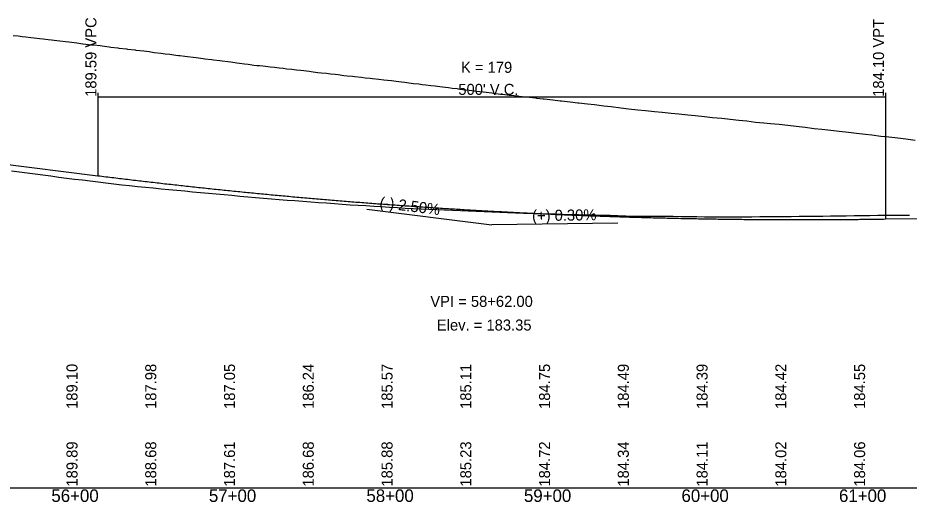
# Model space of a CAD drawing. Extents: x 1876258 to 1932803, y 754739 to 837911.
# Drawn here: x 1882224 to 1882790, y 820541 to 820848 of the extents above; entities that cross this region are included whole.
import ezdxf

# ---------------------------------------------------------------- set-up
doc = ezdxf.new("R2010")
doc.units = 0
for name, color, linetype in [('RD_DDB_GradeTX', 7, 'Continuous'), ('RD_DDB_Profile_EX', 7, 'Continuous'), ('RD_DDB_Profile_Lbl', 7, 'Continuous'), ('RD_DDB_Profile_PR', 7, 'Continuous'), ('RD_DDB_StaTX', 7, 'Continuous'), ('RD_DDB_StripGrade', 7, 'Continuous'), ('RD_DDB_VCLbl', 7, 'Continuous'), ('RD_GPK_Profile_Cell', 7, 'Continuous'), ('RD_Sketch1', 7, 'Continuous')]:
    doc.layers.add(name, color=color, linetype=linetype)

msp = doc.modelspace()

# ---------------------------------------------------------------- linework, layer by layer
at = {"layer": 'RD_DDB_GradeTX'}
for p in [(1882445.7, 820726.77), (1882605.07, 820718.06)]:
    msp.add_line(p, (1882525.08, 820716.86), dxfattribs=at)
at = {"layer": 'RD_DDB_Profile_EX'}
for points in [[(1882220.15, 820751.23), (1882225.15, 820750.53), (1882230.15, 820749.83), (1882235.15, 820749.24), (1882240.15, 820748.65), (1882245.15, 820747.96), (1882250.15, 820747.23), (1882255.15, 820746.53), (1882260.15, 820745.97), (1882265.15, 820745.4), (1882270.15, 820744.77), (1882275.15, 820744.15), (1882280.15, 820743.56), (1882285.15, 820742.97), (1882290.15, 820742.36), (1882295.15, 820741.77), (1882300.15, 820741.26), (1882305.15, 820740.74), (1882310.15, 820740.28), (1882315.15, 820739.84), (1882320.15, 820739.4), (1882325.15, 820738.94), (1882330.15, 820738.44), (1882335.15, 820737.94), (1882340.15, 820737.47), (1882345.15, 820737), (1882350.15, 820736.56), (1882355.15, 820736.12), (1882360.15, 820735.66), (1882365.15, 820735.16), (1882370.15, 820734.66), (1882375.15, 820734.18), (1882380.15, 820733.78), (1882385.15, 820733.38), (1882390.15, 820732.99)], [(1882390.15, 820732.99), (1882395.15, 820732.59), (1882400.15, 820732.25), (1882405.15, 820731.92), (1882410.15, 820731.54), (1882415.15, 820731.16), (1882420.15, 820730.78), (1882425.15, 820730.4), (1882430.15, 820730.03), (1882435.15, 820729.67), (1882440.15, 820729.35), (1882445.15, 820729.09), (1882450.15, 820728.77), (1882455.15, 820728.46), (1882460.15, 820728.16), (1882465.15, 820727.86), (1882470.15, 820727.54), (1882475.15, 820727.22), (1882480.15, 820726.97), (1882485.15, 820726.75), (1882490.15, 820726.57), (1882495.15, 820726.4), (1882500.15, 820726.21), (1882505.15, 820726.03), (1882510.15, 820725.81), (1882515.15, 820725.59), (1882520.15, 820725.37), (1882525.15, 820725.21), (1882530.15, 820724.97), (1882535.15, 820724.72), (1882540.15, 820724.56), (1882545.15, 820724.4), (1882550.15, 820724.25), (1882555.15, 820724.11), (1882560.15, 820723.97), (1882565.15, 820723.83), (1882570.15, 820723.68), (1882575.15, 820723.51), (1882580.15, 820723.39), (1882585.15, 820723.28), (1882590.15, 820723.16), (1882595.15, 820723.05), (1882600.15, 820722.94), (1882605.15, 820722.8), (1882610.15, 820722.65), (1882615.15, 820722.5), (1882620.15, 820722.43), (1882625.15, 820722.38), (1882630.15, 820722.36), (1882635.15, 820722.35), (1882640.15, 820722.32), (1882645.15, 820722.25), (1882650.15, 820722.18), (1882655.15, 820722.11), (1882660.15, 820722.08), (1882665.15, 820722.07), (1882670.15, 820722.06), (1882675.15, 820722.04), (1882680.15, 820722.05), (1882685.15, 820722.05), (1882690.15, 820722.07), (1882695.15, 820722.09), (1882700.15, 820722.11), (1882705.15, 820722.14), (1882710.15, 820722.17), (1882715.15, 820722.24), (1882720.15, 820722.31), (1882725.15, 820722.38), (1882730.15, 820722.45), (1882735.15, 820722.51), (1882740.15, 820722.57), (1882745.15, 820722.64), (1882750.15, 820722.7), (1882755.15, 820722.77), (1882760.15, 820722.84), (1882765.15, 820722.91), (1882770.15, 820722.97), (1882775.15, 820722.99), (1882780.15, 820723), (1882785.15, 820723.01), (1882790.15, 820723.03)]]:
    msp.add_lwpolyline(points, dxfattribs=at)
at = {"layer": 'RD_DDB_Profile_PR'}
for p, q in [((1881558.08, 820837.6), (1882275.08, 820748.07)), ((1882775.08, 820720.61), (1883513.81, 820731.69))]:
    msp.add_line(p, q, dxfattribs=at)
msp.add_spline([(1882275.08, 820748.07), (1882285.08, 820746.84), (1882295.08, 820745.63), (1882305.08, 820744.45), (1882315.08, 820743.3), (1882325.08, 820742.18), (1882335.08, 820741.08), (1882345.08, 820740.02), (1882355.08, 820738.98), (1882365.08, 820737.97), (1882375.08, 820736.98), (1882385.08, 820736.03), (1882395.08, 820735.1), (1882405.08, 820734.2), (1882415.08, 820733.33), (1882425.08, 820732.49), (1882435.08, 820731.67), (1882445.08, 820730.89), (1882455.08, 820730.13), (1882465.08, 820729.4), (1882475.08, 820728.69), (1882485.08, 820728.02), (1882495.08, 820727.37), (1882505.08, 820726.75), (1882515.08, 820726.16), (1882525.08, 820725.6), (1882535.08, 820725.06), (1882545.08, 820724.55), (1882555.08, 820724.08), (1882565.08, 820723.62), (1882575.08, 820723.2), (1882585.08, 820722.8), (1882595.08, 820722.44), (1882605.08, 820722.1), (1882615.08, 820721.79), (1882625.08, 820721.5), (1882635.08, 820721.25), (1882645.08, 820721.02), (1882655.08, 820720.82), (1882665.08, 820720.65), (1882675.08, 820720.5), (1882685.08, 820720.39), (1882695.08, 820720.3), (1882705.08, 820720.24), (1882715.08, 820720.21), (1882725.08, 820720.21), (1882735.08, 820720.23), (1882745.08, 820720.28), (1882755.08, 820720.36), (1882765.08, 820720.47), (1882775.08, 820720.61)], degree=3, dxfattribs=at)
at = {"layer": 'RD_DDB_VCLbl'}
for p, q in [((1882275.08, 820800.57), (1882275.08, 820748.07)), ((1882775.08, 820800.57), (1882775.08, 820720.61)), ((1882275.08, 820798.07), (1882775.08, 820798.07))]:
    msp.add_line(p, q, dxfattribs=at)
at = {"layer": 'RD_GPK_Profile_Cell'}
msp.add_line((1878363.08, 820550.13), (1884763.08, 820550.13), dxfattribs=at)
at = {"layer": 'RD_Sketch1'}
msp.add_lwpolyline([(1882221.33, 820837), (1882224.33, 820836.68), (1882226.87, 820836.38), (1882229.17, 820836.11), (1882232.39, 820835.75), (1882234.62, 820835.51), (1882237.92, 820835.13), (1882240.2, 820834.86), (1882243.46, 820834.45), (1882245.65, 820834.16), (1882248.97, 820833.77), (1882250.92, 820833.54), (1882254.48, 820833.14), (1882256.58, 820832.9), (1882260.02, 820832.48), (1882261.71, 820832.27), (1882265.55, 820831.79), (1882267.28, 820831.57), (1882271.05, 820831.14), (1882272.4, 820830.99), (1882276.56, 820830.56), (1882277.77, 820830.44), (1882282.14, 820829.81), (1882283.18, 820829.66), (1882287.64, 820829.11), (1882288.4, 820829.01), (1882293.14, 820828.5), (1882293.86, 820828.42), (1882298.68, 820827.82), (1882299.08, 820827.77), (1882304.14, 820827.22), (1882304.21, 820827.21), (1882307.5, 820826.79), (1882309.77, 820826.43), (1882310.84, 820826.26), (1882315.25, 820825.72), (1882317.63, 820825.43), (1882320.77, 820825.05), (1882324.6, 820824.6), (1882326.29, 820824.41), (1882327, 820824.32), (1882330.19, 820823.9), (1882331.83, 820823.69), (1882335.51, 820823.21), (1882337.35, 820822.97), (1882341.83, 820822.41), (1882342.87, 820822.28), (1882347.3, 820821.72), (1882348.4, 820821.58), (1882352.5, 820821.06), (1882353.91, 820820.9), (1882357.49, 820820.48), (1882359.45, 820820.22), (1882363.24, 820819.73), (1882364.99, 820819.48), (1882368.18, 820819.02), (1882370.5, 820818.71), (1882374.12, 820818.22), (1882375.98, 820818.04), (1882377.7, 820817.87), (1882379.67, 820817.68), (1882381.51, 820817.47), (1882384.48, 820817.14), (1882387.04, 820816.86), (1882390.09, 820816.52), (1882392.57, 820816.24), (1882395, 820815.95), (1882398.09, 820815.59), (1882401.08, 820815.24), (1882403.61, 820814.95), (1882405.74, 820814.71), (1882409.15, 820814.28), (1882411.72, 820813.95), (1882414.65, 820813.63), (1882416.75, 820813.4), (1882420.17, 820813.04), (1882422.73, 820812.76), (1882425.72, 820812.4), (1882427.5, 820812.18), (1882431.24, 820811.71), (1882433.28, 820811.45), (1882436.74, 820811.1), (1882437.99, 820810.97), (1882442.28, 820810.48), (1882444.61, 820810.21), (1882447.79, 820809.87), (1882449.29, 820809.7), (1882453.32, 820809.26), (1882456.5, 820808.9), (1882458.84, 820808.65), (1882461.32, 820808.37), (1882464.38, 820807.99), (1882467.7, 820807.58), (1882469.89, 820807.32), (1882472.42, 820807.03), (1882475.43, 820806.65), (1882478.67, 820806.24), (1882480.94, 820805.97), (1882483.21, 820805.71), (1882486.46, 820805.33), (1882489.06, 820805.02), (1882491.99, 820804.68), (1882493.69, 820804.48), (1882497.53, 820803.98), (1882499.93, 820803.66), (1882503.04, 820803.28), (1882504.89, 820803.05), (1882508.58, 820802.54), (1882510.72, 820802.24), (1882514.08, 820801.86), (1882515.37, 820801.71), (1882519.59, 820801.26), (1882521.56, 820801.05), (1882525.13, 820800.62), (1882526.25, 820800.48), (1882530.67, 820799.88), (1882532.12, 820799.68), (1882536.16, 820799.25), (1882536.93, 820799.17), (1882541.69, 820798.63), (1882542.34, 820798.55), (1882546.79, 820798.04), (1882547.21, 820797.99), (1882552.74, 820797.38), (1882553.39, 820797.31), (1882557.69, 820796.89), (1882558.27, 820796.82), (1882563.79, 820796.16), (1882563.85, 820796.16), (1882568.45, 820795.63), (1882569.32, 820795.53), (1882574.84, 820794.87), (1882574.92, 820794.86), (1882579.75, 820794.3), (1882580.35, 820794.23), (1882585.81, 820793.61), (1882585.87, 820793.61), (1882590.36, 820793.13), (1882596.29, 820792.37), (1882600.82, 820791.86), (1882607, 820791.11), (1882611.79, 820790.54), (1882617.81, 820789.95), (1882622.75, 820789.43), (1882628.36, 820788.83), (1882633.31, 820788.27), (1882638.98, 820787.73), (1882643.86, 820787.27), (1882649.58, 820786.68), (1882654.27, 820786.2), (1882660.16, 820785.55), (1882665.25, 820785.04), (1882671.11, 820784.49), (1882676.43, 820783.93), (1882681.91, 820783.37), (1882686.9, 820782.81), (1882692.54, 820782.12), (1882695.07, 820781.85), (1882697.85, 820781.55), (1882701.98, 820781.16), (1882707.53, 820780.68), (1882712.97, 820780.14), (1882718.41, 820779.48), (1882723.95, 820778.75), (1882729.76, 820778.09), (1882734.62, 820777.56), (1882740.3, 820776.91), (1882745.71, 820776.27), (1882751.57, 820775.63), (1882756.71, 820775.1), (1882762.29, 820774.45), (1882766.28, 820773.94), (1882772.16, 820773.21), (1882777.13, 820772.63), (1882782.76, 820772), (1882788.01, 820771.43), (1882793.77, 820770.7)], dxfattribs=at)
msp.add_lwpolyline([(1882221.33, 820837), (1882224.33, 820836.68), (1882226.87, 820836.38), (1882229.17, 820836.11), (1882232.39, 820835.75), (1882234.62, 820835.51), (1882237.92, 820835.13), (1882240.2, 820834.86), (1882243.46, 820834.45), (1882245.65, 820834.16), (1882248.97, 820833.77), (1882250.92, 820833.54), (1882254.48, 820833.14), (1882256.58, 820832.9), (1882260.02, 820832.48), (1882261.71, 820832.27), (1882265.55, 820831.79), (1882267.28, 820831.57), (1882271.05, 820831.14), (1882272.4, 820830.99), (1882276.56, 820830.56), (1882277.77, 820830.44), (1882282.14, 820829.81), (1882283.18, 820829.66), (1882287.64, 820829.11), (1882288.4, 820829.01), (1882293.14, 820828.5), (1882293.86, 820828.42), (1882298.68, 820827.82), (1882299.08, 820827.77), (1882304.14, 820827.22), (1882304.21, 820827.21), (1882307.5, 820826.79), (1882309.77, 820826.43), (1882310.84, 820826.26), (1882315.25, 820825.72), (1882317.63, 820825.43), (1882320.77, 820825.05), (1882324.6, 820824.6), (1882326.29, 820824.41), (1882327, 820824.32), (1882330.19, 820823.9), (1882331.83, 820823.69), (1882335.51, 820823.21), (1882337.35, 820822.97), (1882341.83, 820822.41), (1882342.87, 820822.28), (1882347.3, 820821.72), (1882348.4, 820821.58), (1882352.5, 820821.06), (1882353.91, 820820.9), (1882357.49, 820820.48), (1882359.45, 820820.22), (1882363.24, 820819.73), (1882364.99, 820819.48), (1882368.18, 820819.02), (1882370.5, 820818.71), (1882374.12, 820818.22), (1882375.98, 820818.04), (1882377.7, 820817.87), (1882379.67, 820817.68), (1882381.51, 820817.47), (1882384.48, 820817.14), (1882387.04, 820816.86), (1882390.09, 820816.52), (1882392.57, 820816.24), (1882395, 820815.95), (1882398.09, 820815.59), (1882401.08, 820815.24), (1882403.61, 820814.95), (1882405.74, 820814.71), (1882409.15, 820814.28), (1882411.72, 820813.95), (1882414.65, 820813.63), (1882416.75, 820813.4), (1882420.17, 820813.04), (1882422.73, 820812.76), (1882425.72, 820812.4), (1882427.5, 820812.18), (1882431.24, 820811.71), (1882433.28, 820811.45), (1882436.74, 820811.1), (1882437.99, 820810.97), (1882442.28, 820810.48), (1882444.61, 820810.21), (1882447.79, 820809.87), (1882449.29, 820809.7), (1882453.32, 820809.26), (1882456.5, 820808.9), (1882458.84, 820808.65), (1882461.32, 820808.37), (1882464.38, 820807.99), (1882467.7, 820807.58), (1882469.89, 820807.32), (1882472.42, 820807.03), (1882475.43, 820806.65), (1882478.67, 820806.24), (1882480.94, 820805.97), (1882483.21, 820805.71), (1882486.46, 820805.33), (1882489.06, 820805.02), (1882491.99, 820804.68), (1882493.69, 820804.48), (1882497.53, 820803.98), (1882499.93, 820803.66), (1882503.04, 820803.28), (1882504.89, 820803.05), (1882508.58, 820802.54), (1882510.72, 820802.24), (1882514.08, 820801.86), (1882515.37, 820801.71), (1882519.59, 820801.26), (1882521.56, 820801.05), (1882525.13, 820800.62), (1882526.25, 820800.48), (1882530.67, 820799.88), (1882532.12, 820799.68), (1882536.16, 820799.25), (1882536.93, 820799.17), (1882541.69, 820798.63), (1882542.34, 820798.55), (1882546.79, 820798.04), (1882547.21, 820797.99), (1882552.74, 820797.38), (1882553.39, 820797.31), (1882557.69, 820796.89), (1882558.27, 820796.82), (1882563.79, 820796.16), (1882563.85, 820796.16), (1882568.45, 820795.63), (1882569.32, 820795.53), (1882574.84, 820794.87), (1882574.92, 820794.86), (1882579.75, 820794.3), (1882580.35, 820794.23), (1882585.81, 820793.61), (1882585.87, 820793.61), (1882590.36, 820793.13), (1882596.29, 820792.37), (1882600.82, 820791.86), (1882607, 820791.11), (1882611.79, 820790.54), (1882617.81, 820789.95), (1882622.75, 820789.43), (1882628.36, 820788.83), (1882633.31, 820788.27), (1882638.98, 820787.73), (1882643.86, 820787.27), (1882649.58, 820786.68), (1882654.27, 820786.2), (1882660.16, 820785.55), (1882665.25, 820785.04), (1882671.11, 820784.49), (1882676.43, 820783.93), (1882681.91, 820783.37), (1882686.9, 820782.81), (1882692.54, 820782.12), (1882695.07, 820781.85), (1882697.85, 820781.55), (1882701.98, 820781.16), (1882707.53, 820780.68), (1882712.97, 820780.14), (1882718.41, 820779.48), (1882723.95, 820778.75), (1882729.76, 820778.09), (1882734.62, 820777.56), (1882740.3, 820776.91), (1882745.71, 820776.27), (1882751.57, 820775.63), (1882756.71, 820775.1), (1882762.29, 820774.45), (1882766.28, 820773.94), (1882772.16, 820773.21), (1882777.13, 820772.63), (1882782.76, 820772), (1882788.01, 820771.43), (1882793.77, 820770.7)], dxfattribs=at)
msp.add_lwpolyline([(1882221.33, 820837), (1882224.33, 820836.68), (1882226.87, 820836.38), (1882229.17, 820836.11), (1882232.39, 820835.75), (1882234.62, 820835.51), (1882237.92, 820835.13), (1882240.2, 820834.86), (1882243.46, 820834.45), (1882245.65, 820834.16), (1882248.97, 820833.77), (1882250.92, 820833.54), (1882254.48, 820833.14), (1882256.58, 820832.9), (1882260.02, 820832.48), (1882261.71, 820832.27), (1882265.55, 820831.79), (1882267.28, 820831.57), (1882271.05, 820831.14), (1882272.4, 820830.99), (1882276.56, 820830.56), (1882277.77, 820830.44), (1882282.14, 820829.81), (1882283.18, 820829.66), (1882287.64, 820829.11), (1882288.4, 820829.01), (1882293.14, 820828.5), (1882293.86, 820828.42), (1882298.68, 820827.82), (1882299.08, 820827.77), (1882304.14, 820827.22), (1882304.21, 820827.21), (1882307.5, 820826.79), (1882309.77, 820826.43), (1882310.84, 820826.26), (1882315.25, 820825.72), (1882317.63, 820825.43), (1882320.77, 820825.05), (1882324.6, 820824.6), (1882326.29, 820824.41), (1882327, 820824.32), (1882330.19, 820823.9), (1882331.83, 820823.69), (1882335.51, 820823.21), (1882337.35, 820822.97), (1882341.83, 820822.41), (1882342.87, 820822.28), (1882347.3, 820821.72), (1882348.4, 820821.58), (1882352.5, 820821.06), (1882353.91, 820820.9), (1882357.49, 820820.48), (1882359.45, 820820.22), (1882363.24, 820819.73), (1882364.99, 820819.48), (1882368.18, 820819.02), (1882370.5, 820818.71), (1882374.12, 820818.22), (1882375.98, 820818.04), (1882377.7, 820817.87), (1882379.67, 820817.68), (1882381.51, 820817.47), (1882384.48, 820817.14), (1882387.04, 820816.86), (1882390.09, 820816.52), (1882392.57, 820816.24), (1882395, 820815.95), (1882398.09, 820815.59), (1882401.08, 820815.24), (1882403.61, 820814.95), (1882405.74, 820814.71), (1882409.15, 820814.28), (1882411.72, 820813.95), (1882414.65, 820813.63), (1882416.75, 820813.4), (1882420.17, 820813.04), (1882422.73, 820812.76), (1882425.72, 820812.4), (1882427.5, 820812.18), (1882431.24, 820811.71), (1882433.28, 820811.45), (1882436.74, 820811.1), (1882437.99, 820810.97), (1882442.28, 820810.48), (1882444.61, 820810.21), (1882447.79, 820809.87), (1882449.29, 820809.7), (1882453.32, 820809.26), (1882456.5, 820808.9), (1882458.84, 820808.65), (1882461.32, 820808.37), (1882464.38, 820807.99), (1882467.7, 820807.58), (1882469.89, 820807.32), (1882472.42, 820807.03), (1882475.43, 820806.65), (1882478.67, 820806.24), (1882480.94, 820805.97), (1882483.21, 820805.71), (1882486.46, 820805.33), (1882489.06, 820805.02), (1882491.99, 820804.68), (1882493.69, 820804.48), (1882497.53, 820803.98), (1882499.93, 820803.66), (1882503.04, 820803.28), (1882504.89, 820803.05), (1882508.58, 820802.54), (1882510.72, 820802.24), (1882514.08, 820801.86), (1882515.37, 820801.71), (1882519.59, 820801.26), (1882521.56, 820801.05), (1882525.13, 820800.62), (1882526.25, 820800.48), (1882530.67, 820799.88), (1882532.12, 820799.68), (1882536.16, 820799.25), (1882536.93, 820799.17), (1882541.69, 820798.63), (1882542.34, 820798.55), (1882546.79, 820798.04), (1882547.21, 820797.99), (1882552.74, 820797.38), (1882553.39, 820797.31), (1882557.69, 820796.89), (1882558.27, 820796.82), (1882563.79, 820796.16), (1882563.85, 820796.16), (1882568.45, 820795.63), (1882569.32, 820795.53), (1882574.84, 820794.87), (1882574.92, 820794.86), (1882579.75, 820794.3), (1882580.35, 820794.23), (1882585.81, 820793.61), (1882585.87, 820793.61), (1882590.36, 820793.13), (1882596.29, 820792.37), (1882600.82, 820791.86), (1882607, 820791.11), (1882611.79, 820790.54), (1882617.81, 820789.95), (1882622.75, 820789.43), (1882628.36, 820788.83), (1882633.31, 820788.27), (1882638.98, 820787.73), (1882643.86, 820787.27), (1882649.58, 820786.68), (1882654.27, 820786.2), (1882660.16, 820785.55), (1882665.25, 820785.04), (1882671.11, 820784.49), (1882676.43, 820783.93), (1882681.91, 820783.37), (1882686.9, 820782.81), (1882692.54, 820782.12), (1882695.07, 820781.85), (1882697.85, 820781.55), (1882701.98, 820781.16), (1882707.53, 820780.68), (1882712.97, 820780.14), (1882718.41, 820779.48), (1882723.95, 820778.75), (1882729.76, 820778.09), (1882734.62, 820777.56), (1882740.3, 820776.91), (1882745.71, 820776.27), (1882751.57, 820775.63), (1882756.71, 820775.1), (1882762.29, 820774.45), (1882766.28, 820773.94), (1882772.16, 820773.21), (1882777.13, 820772.63), (1882782.76, 820772), (1882788.01, 820771.43), (1882793.77, 820770.7)], dxfattribs=at)

# ---------------------------------------------------------------- texts
at = {"layer": 'RD_DDB_GradeTX'}
for s, rotation, p in [('(-) 2.50%', 352.8826, (1882453.57, 820727.8)), ('(+) 0.30%', 0.8594, (1882550.72, 820719.24))]:
    msp.add_text(s, height=7, rotation=rotation, dxfattribs=at).set_placement(p)
at = {"layer": 'RD_DDB_Profile_Lbl'}
for s, p in [('VPI = 58+62.00', (1882486.06, 820664.86)), ('Elev. = 183.35', (1882490.22, 820649.86))]:
    msp.add_text(s, height=7, dxfattribs=at).set_placement(p)
at = {"layer": 'RD_DDB_StaTX'}
for s, p in [('56+00', (1882245.49, 820541.13)), ('57+00', (1882345.49, 820541.13)), ('58+00', (1882445.49, 820541.13)), ('59+00', (1882545.49, 820541.13)), ('60+00', (1882645.49, 820541.13)), ('61+00', (1882745.49, 820541.13))]:
    msp.add_text(s, height=8, dxfattribs=at).set_placement(p)
at = {"layer": 'RD_DDB_StripGrade'}
for s, p in [('189.59 VPC', (1882274.08, 820798.07)), ('184.10 VPT', (1882774.08, 820798.07)), ('189.10', (1882262.08, 820600.13)), ('187.98', (1882312.08, 820600.13)), ('187.05', (1882362.08, 820600.13)), ('186.24', (1882412.08, 820600.13)), ('185.57', (1882462.08, 820600.13)), ('185.11', (1882512.08, 820600.13)), ('184.75', (1882562.08, 820600.13)), ('184.49', (1882612.08, 820600.13)), ('184.39', (1882662.08, 820600.13)), ('184.42', (1882712.08, 820600.13)), ('184.55', (1882762.08, 820600.13)), ('189.89', (1882262.08, 820550.88)), ('188.68', (1882312.08, 820550.88)), ('187.61', (1882362.08, 820550.88)), ('186.68', (1882412.08, 820550.88)), ('185.88', (1882462.08, 820550.88)), ('185.23', (1882512.08, 820550.88)), ('184.72', (1882562.08, 820550.88)), ('184.34', (1882612.08, 820550.88)), ('184.11', (1882662.08, 820550.88)), ('184.02', (1882712.08, 820550.88)), ('184.06', (1882762.08, 820550.88))]:
    msp.add_text(s, height=7, rotation=90, dxfattribs=at).set_placement(p)
at = {"layer": 'RD_DDB_VCLbl'}
for s, p in [('K = 179', (1882505.52, 820813.32)), ("500' V.C.", (1882503.83, 820799.32))]:
    msp.add_text(s, height=7, dxfattribs=at).set_placement(p)

doc.saveas('drawing.dxf')
